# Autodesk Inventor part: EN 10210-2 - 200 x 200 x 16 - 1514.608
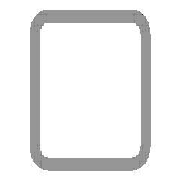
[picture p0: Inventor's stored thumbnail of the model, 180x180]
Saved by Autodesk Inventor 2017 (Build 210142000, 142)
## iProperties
IsCustomPart: 1
Created: 2017-11
Part Number: EN 10210-2 - 200 x 200 x 16 - 1514.608
Material: Steel, Mild
Description: Tube
Document SubType Name: Modeling
Standard: DIN
Designer: iusti
Standard Revision: 2006-07
Standards Organization: DIN
Language: en-US
Size Designation: 200 x 200 x 16
Categories: <MemberInstance><Categories><Category DisplayName="Structural Shapes" InternalName="089c4875-fa83-4c05-b084-43b9cc11f5ed" Mnemonic="GRDR"><CategoryParameter Dis
Stock Number: 200 x 200 x 16
Density: 7.85 g/cm^3
Appearance: Semi-Polished
Mass: 136747 g
Surface Area: 21484.9 cm^2
Volume: 17420 cm^3
_CCFamilyMember: 94
_CCFamilyDisplayName: DIN EN 10210-2 (Square) - Tube — Sizes in parentheses have been withdrawn
_FrameMemberDoc: Frame Member File
_Version: 15.0.0
_GetPNFromCC: 1
G_L: 1514.608 mm
G_W: 200.000 mm
G_H: 200.000 mm
+F9030F02-54E8-4A48-A29A-107C7036A7ED+CUTDETAIL1: Cut
Author: iusti
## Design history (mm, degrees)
node "Start plane"
node "End plane"
sketch "Sketch"
  geometry: L1 (-100, -76)-(-100, 76); L2 (-76, 100)-(76, 100); L3 (100, 76)-(100, -76); L4 (76, -100)-(-76, -100); L5 (-68, 84)-(68, 84); L6 (84, 68)-(84, -68); L7 (68, -84)-(-68, -84); L8 (-84, -68)-(-84, 68); L9 (0, 146.959)-(0, -146.959) reference; L10 (-146.959, 0)-(146.959, 0) reference; A1 r 24 centre (-76, -76) between (-100, -76) and (-76, -100); A2 r 24 centre (-76, 76) between (-76, 100) and (-100, 76); A3 r 24 centre (76, 76) between (100, 76) and (76, 100); A4 r 24 centre (76, -76) between (76, -100) and (100, -76); A5 r 16 centre (-68, -68) between (-84, -68) and (-68, -84); A6 r 16 centre (-68, 68) between (-68, 84) and (-84, 68); A7 r 16 centre (68, 68) between (84, 68) and (68, 84); A8 r 16 centre (68, -68) between (68, -84) and (84, -68)
  constraints: 16 end point, 16 point on circle, 16 tangent, 8 centre point, 6 equal radius, 4 parallel, 2 perpendicular, 2 other
  dimensions: "d7" = 24 radius of A1 (= G_IR); "d10" = 200 distance between parallel lines of L2 L4 (= G_H); "d11" = 200 distance between parallel lines of L1 L3 (= G_W); "d12" = 16 distance between parallel lines of L3 L6 (= G_T); "d15" = 100 distance between parallel lines of L2 L10 (= 0.5 x d10); "d16" = 100 distance between parallel lines of L9 L3 (= 0.5 x d11); "d19" = 16 radius of A5 (= G_T); "d20" = 16 distance between parallel lines of L4 L7 (= G_T)
extrude "Body" new body sketch "Sketch" stored distance "d3" = 1514.60835 (= G_L); taper "d4" = 0 deg
node "Driven Length"
  sketch "Sketch3"
    geometry: L1 (0, 0)-(10, 0) reference
    constraints: 2 end point, 1 horizontal
  workplane "Work Plane3"
  sketch "Sketch4"
    geometry: L1 (-2, 0)-(12, 0) reference; L2 (-2, 1514.608)-(12, 1514.608) reference
    dimensions: "d18" = 1514.60835 distance between parallel lines of L1 L2 (derived)
workplane "Work Plane4"
split "Split1"
body "Solid1"
other parameters: "G_W" = 200 [user parameter; used in 1 equation term], "G_H" = 200 [user parameter; used in 1 equation term], "G_T" = 16 [user parameter; used in 3 equation terms], "G_IR" = 24 [user parameter; used in 1 equation term], "G_L" = 1514.60835 (= d18) [user parameter; used in 1 equation term], "G_OFFSET_START" = 0 [user parameter; used in 1 equation term], "d13" = 0 (computed from G_OFFSET_START), "d14" = 1514.60835 (= G_OFFSET_END + B_L), "B_L" = 1614.60835 [user parameter; used in 1 equation term], "d17" = 90 deg
